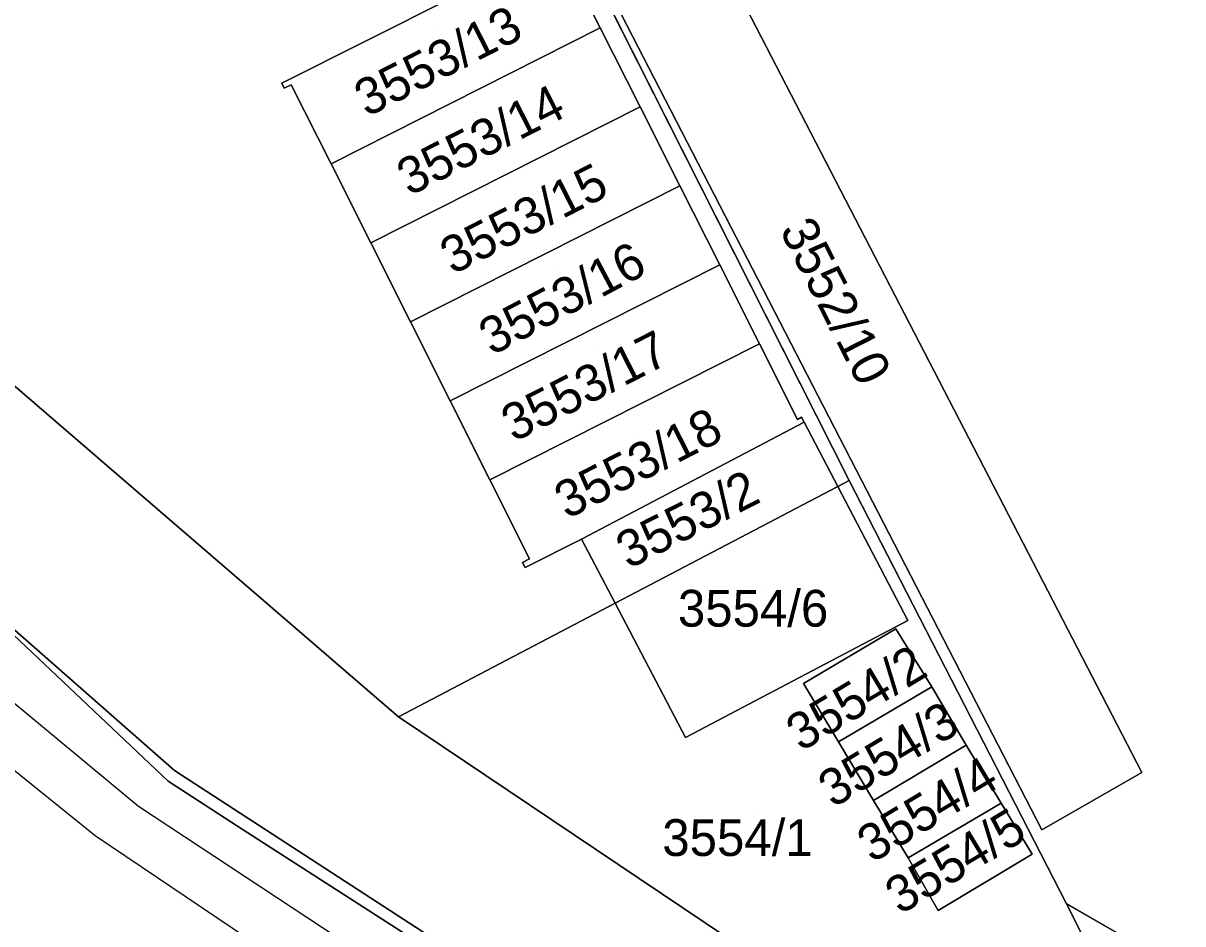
# Model space of a CAD drawing. Extents: x -262657 to -261595, y -1238015 to -1237156.
# Drawn here: x -262494.6 to -262431.6, y -1237484.4 to -1237435.4 of the extents above; entities that cross this region are included whole.
import ezdxf

# ---------------------------------------------------------------- set-up
doc = ezdxf.new("R2010")
doc.units = 0
for name, color, linetype in [('body_kn', 7, 'Continuous'), ('kladpar_druhypozemkov', 7, 'Continuous'), ('kladpar_hranice', 7, 'Continuous'), ('kladpar_parcelnecisla', 7, 'Continuous'), ('kladpar_plochy', 7, 'Continuous'), ('zappar_hrandruhpozemk', 7, 'Continuous')]:
    doc.layers.add(name, color=color, linetype=linetype)

msp = doc.modelspace()

# ---------------------------------------------------------------- linework, layer by layer
at = {"layer": 'body_kn'}
for p, q in [((-262463.26, -1237435.69), (-262463.26, -1237435.69)), ((-262463.26, -1237435.69), (-262463.26, -1237435.69)), ((-262480.58, -1237438.69), (-262480.58, -1237438.69)), ((-262480.44, -1237438.97), (-262480.44, -1237438.97)), ((-262480.06, -1237438.78), (-262480.06, -1237438.78)), ((-262461.09, -1237439.99), (-262461.09, -1237439.99)), ((-262461.09, -1237439.99), (-262461.09, -1237439.99)), ((-262477.9, -1237443.08), (-262477.9, -1237443.08)), ((-262458.93, -1237444.28), (-262458.93, -1237444.28)), ((-262458.93, -1237444.28), (-262458.93, -1237444.28)), ((-262475.74, -1237447.37), (-262475.74, -1237447.37)), ((-262456.76, -1237448.58), (-262456.76, -1237448.58)), ((-262456.76, -1237448.58), (-262456.76, -1237448.58)), ((-262473.58, -1237451.67), (-262473.58, -1237451.67)), ((-262454.6, -1237452.87), (-262454.6, -1237452.87)), ((-262454.6, -1237452.87), (-262454.6, -1237452.87)), ((-262471.42, -1237455.97), (-262471.42, -1237455.97)), ((-262452.53, -1237456.98), (-262452.53, -1237456.98)), ((-262452.31, -1237456.86), (-262452.31, -1237456.86)), ((-262452.17, -1237457.13), (-262452.17, -1237457.13)), ((-262469.26, -1237460.27), (-262469.26, -1237460.27)), ((-262450.34, -1237460.63), (-262450.34, -1237460.63)), ((-262449.72, -1237460.31), (-262449.72, -1237460.31)), ((-262464.28, -1237463.5), (-262464.28, -1237463.5)), ((-262467.1, -1237464.57), (-262467.1, -1237464.57)), ((-262467.48, -1237464.76), (-262467.48, -1237464.76)), ((-262467.34, -1237465.04), (-262467.34, -1237465.04)), ((-262462.45, -1237466.98), (-262462.45, -1237466.98)), ((-262446.52, -1237467.91), (-262446.52, -1237467.91)), ((-262447.18, -1237468.37), (-262447.18, -1237468.37)), ((-262452.2, -1237471.34), (-262452.2, -1237471.34)), ((-262445.23, -1237471.53), (-262445.23, -1237471.53)), ((-262474.23, -1237473.15), (-262474.23, -1237473.15)), ((-262458.62, -1237474.27), (-262458.62, -1237474.27)), ((-262450.3, -1237474.52), (-262450.3, -1237474.52)), ((-262450.3, -1237474.52), (-262450.3, -1237474.52)), ((-262443.36, -1237474.7), (-262443.36, -1237474.7)), ((-262486.42, -1237476.08), (-262486.42, -1237476.08)), ((-262433.8, -1237476.18), (-262433.8, -1237476.18)), ((-262486.75, -1237476.66), (-262486.75, -1237476.66)), ((-262448.4, -1237477.7), (-262448.4, -1237477.7)), ((-262488.38, -1237478.01), (-262488.38, -1237478.01)), ((-262488.38, -1237478.01), (-262488.38, -1237478.01)), ((-262441.45, -1237477.85), (-262441.45, -1237477.85)), ((-262441.45, -1237477.85), (-262441.45, -1237477.85)), ((-262490.72, -1237479.63), (-262490.72, -1237479.63)), ((-262482.67, -1237479.3), (-262482.67, -1237479.3)), ((-262439.24, -1237479.29), (-262439.24, -1237479.29)), ((-262446.51, -1237480.83), (-262446.51, -1237480.83)), ((-262439.76, -1237480.62), (-262439.76, -1237480.62)), ((-262437.9, -1237483.33), (-262437.9, -1237483.33)), ((-262437.9, -1237483.33), (-262437.9, -1237483.33)), ((-262444.88, -1237483.68), (-262444.88, -1237483.68))]:
    msp.add_line(p, q, dxfattribs=at)
at = {"layer": 'kladpar_druhypozemkov'}
for p, q in [((-262472.01, -1237435.78), (-262472.01, -1237435.78)), ((-262470.02, -1237440.27), (-262470.02, -1237440.27)), ((-262467.87, -1237444.74), (-262467.87, -1237444.74)), ((-262465.57, -1237448.92), (-262465.57, -1237448.92)), ((-262449.78, -1237450.42), (-262449.78, -1237450.42)), ((-262463.49, -1237453.15), (-262463.49, -1237453.15)), ((-262461.19, -1237457.73), (-262461.19, -1237457.73)), ((-262458.49, -1237461.26), (-262458.49, -1237461.26)), ((-262454.52, -1237466.22), (-262454.52, -1237466.22)), ((-262449.49, -1237470.42), (-262449.49, -1237470.42)), ((-262447.56, -1237473.71), (-262447.56, -1237473.71)), ((-262445.67, -1237477.1), (-262445.67, -1237477.1)), ((-262454.87, -1237478.37), (-262454.87, -1237478.37)), ((-262443.64, -1237480.28), (-262443.64, -1237480.28))]:
    msp.add_line(p, q, dxfattribs=at)
at = {"layer": 'kladpar_hranice'}
msp.add_line((-262428.89, -1237501.14), (-262437.9, -1237483.33), dxfattribs=at)
for points in [[(-262437.9, -1237483.33), (-262449.72, -1237460.31), (-262464.28, -1237431.46), (-262469.6, -1237420.93), (-262478.29, -1237403.67), (-262478.73, -1237402.85), (-262506.09, -1237404.44), (-262514.95, -1237386.75), (-262519.84, -1237377.16), (-262513.51, -1237373.66), (-262507.3, -1237370.26), (-262500.71, -1237366.65), (-262500.15, -1237367.7), (-262490.13, -1237386.72), (-262486.03, -1237384.56), (-262484.61, -1237387.26), (-262481.8, -1237385.78), (-262483.22, -1237383.08), (-262479.4, -1237381.2)], [(-262395.88, -1237531.76), (-262402.36, -1237530.54), (-262422.32, -1237519.41), (-262447.06, -1237506.81), (-262470.88, -1237493), (-262490.72, -1237479.63), (-262514.25, -1237460.66), (-262531.79, -1237443.64), (-262573.35, -1237398.14), (-262590.88, -1237375.27)], [(-262562.79, -1237383.63), (-262550.17, -1237397.64), (-262523.77, -1237426.48), (-262525.24, -1237427.48), (-262521.65, -1237431.15), (-262511.59, -1237440.19), (-262501.92, -1237449.31), (-262474.23, -1237473.15), (-262426.57, -1237505.16), (-262417.76, -1237512.55), (-262418.9, -1237513.84), (-262420.4, -1237513.14), (-262442.59, -1237502.2), (-262453.27, -1237496.92), (-262463.93, -1237490.63), (-262472.55, -1237485.09), (-262486.42, -1237476.08), (-262499.91, -1237464.23)], [(-262576.16, -1237389.82), (-262565.17, -1237400.69), (-262553.5, -1237412.44), (-262535.69, -1237430.45), (-262521.77, -1237443.76), (-262511.25, -1237453.79), (-262499.91, -1237464.23), (-262486.75, -1237476.66), (-262482.67, -1237479.3), (-262464.31, -1237491.1), (-262455.93, -1237496.51), (-262449.45, -1237500.04), (-262419.93, -1237515), (-262406.23, -1237521.95), (-262395.88, -1237531.76)], [(-262501.01, -1237414.95), (-262493.57, -1237411.26), (-262490.55, -1237417.14), (-262482.07, -1237412.85), (-262480.81, -1237415.34), (-262479.46, -1237418.02), (-262478.12, -1237420.68), (-262476.78, -1237423.32), (-262475.43, -1237425.99), (-262474.07, -1237428.68), (-262472.71, -1237431.38), (-262471.37, -1237434.05), (-262480.58, -1237438.69), (-262480.44, -1237438.97), (-262480.06, -1237438.78), (-262477.9, -1237443.08), (-262475.74, -1237447.37), (-262473.58, -1237451.67), (-262471.42, -1237455.97), (-262469.26, -1237460.27), (-262467.1, -1237464.57), (-262467.48, -1237464.76), (-262467.34, -1237465.04), (-262464.28, -1237463.5)], [(-262465.7, -1237431.19), (-262465.34, -1237431.01), (-262465.21, -1237431.27), (-262465.43, -1237431.39), (-262463.26, -1237435.69), (-262477.9, -1237443.08), (-262480.06, -1237438.78), (-262480.44, -1237438.97), (-262480.58, -1237438.69), (-262471.37, -1237434.05), (-262465.7, -1237431.19)], [(-262464.28, -1237431.46), (-262449.72, -1237460.31), (-262450.34, -1237460.63), (-262452.17, -1237457.13), (-262452.31, -1237456.86), (-262452.53, -1237456.98), (-262454.6, -1237452.87), (-262456.76, -1237448.58), (-262458.93, -1237444.28), (-262461.09, -1237439.99), (-262463.26, -1237435.69), (-262465.43, -1237431.39)], [(-262462.11, -1237434.98), (-262456.65, -1237432.03), (-262433.8, -1237476.18), (-262439.24, -1237479.29), (-262462.11, -1237434.98)], [(-262456.65, -1237432.03), (-262462.11, -1237434.98), (-262439.24, -1237479.29), (-262433.8, -1237476.18), (-262456.65, -1237432.03)], [(-262463.26, -1237435.69), (-262461.09, -1237439.99), (-262475.74, -1237447.37), (-262477.9, -1237443.08), (-262463.26, -1237435.69)], [(-262461.09, -1237439.99), (-262458.93, -1237444.28), (-262473.58, -1237451.67), (-262475.74, -1237447.37), (-262461.09, -1237439.99)], [(-262458.93, -1237444.28), (-262456.76, -1237448.58), (-262471.42, -1237455.97), (-262473.58, -1237451.67), (-262458.93, -1237444.28)], [(-262456.76, -1237448.58), (-262454.6, -1237452.87), (-262469.26, -1237460.27), (-262471.42, -1237455.97), (-262456.76, -1237448.58)], [(-262464.28, -1237463.5), (-262462.45, -1237466.98), (-262474.23, -1237473.15), (-262501.92, -1237449.31)], [(-262454.6, -1237452.87), (-262452.53, -1237456.98), (-262452.31, -1237456.86), (-262452.17, -1237457.13), (-262464.28, -1237463.5), (-262467.34, -1237465.04), (-262467.48, -1237464.76), (-262467.1, -1237464.57), (-262469.26, -1237460.27), (-262454.6, -1237452.87)], [(-262450.34, -1237460.63), (-262462.45, -1237466.98), (-262464.28, -1237463.5), (-262452.17, -1237457.13), (-262450.34, -1237460.63)], [(-262428.89, -1237501.14), (-262426.57, -1237505.16), (-262474.23, -1237473.15), (-262462.45, -1237466.98), (-262458.62, -1237474.27), (-262446.52, -1237467.91), (-262450.34, -1237460.63), (-262449.72, -1237460.31), (-262437.9, -1237483.33), (-262428.89, -1237501.14)], [(-262462.45, -1237466.98), (-262450.34, -1237460.63), (-262446.52, -1237467.91), (-262458.62, -1237474.27), (-262462.45, -1237466.98)], [(-262419.93, -1237515), (-262449.45, -1237500.04), (-262455.93, -1237496.51), (-262464.31, -1237491.1), (-262482.67, -1237479.3), (-262486.75, -1237476.66), (-262499.91, -1237464.23), (-262486.42, -1237476.08), (-262472.55, -1237485.09), (-262463.93, -1237490.63), (-262453.27, -1237496.92), (-262442.59, -1237502.2), (-262420.4, -1237513.14), (-262418.9, -1237513.84), (-262419.93, -1237515)], [(-262450.3, -1237474.52), (-262452.2, -1237471.34), (-262447.18, -1237468.37), (-262445.23, -1237471.53), (-262450.3, -1237474.52)], [(-262439.76, -1237480.62), (-262441.45, -1237477.85), (-262443.36, -1237474.7), (-262445.23, -1237471.53), (-262447.18, -1237468.37), (-262452.2, -1237471.34), (-262450.3, -1237474.52), (-262448.4, -1237477.7), (-262446.51, -1237480.83), (-262444.88, -1237483.68), (-262439.76, -1237480.62)], [(-262450.3, -1237474.52), (-262445.23, -1237471.53), (-262443.36, -1237474.7), (-262448.4, -1237477.7), (-262450.3, -1237474.52)], [(-262441.45, -1237477.85), (-262446.51, -1237480.83), (-262448.4, -1237477.7), (-262443.36, -1237474.7), (-262441.45, -1237477.85)], [(-262441.45, -1237477.85), (-262439.76, -1237480.62), (-262444.88, -1237483.68), (-262446.51, -1237480.83), (-262441.45, -1237477.85)], [(-262437.9, -1237483.33), (-262420.61, -1237493.26), (-262428.89, -1237501.14)], [(-262408.93, -1237499.96), (-262420.61, -1237493.26), (-262437.9, -1237483.33)]]:
    msp.add_lwpolyline(points, dxfattribs=at)
at = {"layer": 'kladpar_plochy'}
for p, q in [((-262449.72, -1237460.31), (-262464.28, -1237431.46)), ((-262433.8, -1237476.18), (-262456.65, -1237432.03)), ((-262462.11, -1237434.98), (-262439.24, -1237479.29)), ((-262450.34, -1237460.63), (-262449.72, -1237460.31)), ((-262446.52, -1237467.91), (-262450.34, -1237460.63)), ((-262437.9, -1237483.33), (-262449.72, -1237460.31)), ((-262449.72, -1237460.31), (-262437.9, -1237483.33)), ((-262474.23, -1237473.15), (-262462.45, -1237466.98)), ((-262462.45, -1237466.98), (-262458.62, -1237474.27)), ((-262458.62, -1237474.27), (-262446.52, -1237467.91)), ((-262447.18, -1237468.37), (-262452.2, -1237471.34)), ((-262445.23, -1237471.53), (-262447.18, -1237468.37)), ((-262452.2, -1237471.34), (-262450.3, -1237474.52)), ((-262443.36, -1237474.7), (-262445.23, -1237471.53)), ((-262426.57, -1237505.16), (-262474.23, -1237473.15)), ((-262450.3, -1237474.52), (-262448.4, -1237477.7)), ((-262441.45, -1237477.85), (-262443.36, -1237474.7)), ((-262439.24, -1237479.29), (-262433.8, -1237476.18)), ((-262448.4, -1237477.7), (-262446.51, -1237480.83)), ((-262439.76, -1237480.62), (-262441.45, -1237477.85)), ((-262446.51, -1237480.83), (-262444.88, -1237483.68)), ((-262444.88, -1237483.68), (-262439.76, -1237480.62)), ((-262420.61, -1237493.26), (-262437.9, -1237483.33)), ((-262437.9, -1237483.33), (-262428.89, -1237501.14))]:
    msp.add_line(p, q, dxfattribs=at)
for points in [[(-262395.88, -1237531.76), (-262402.36, -1237530.54), (-262422.32, -1237519.41), (-262447.06, -1237506.81), (-262470.88, -1237493), (-262490.72, -1237479.63), (-262514.25, -1237460.66), (-262531.79, -1237443.64), (-262573.35, -1237398.14), (-262590.88, -1237375.27), (-262576.16, -1237389.82), (-262565.17, -1237400.69), (-262553.5, -1237412.44), (-262535.69, -1237430.45), (-262521.77, -1237443.76), (-262511.25, -1237453.79), (-262499.91, -1237464.23), (-262486.75, -1237476.66), (-262482.67, -1237479.3), (-262464.31, -1237491.1), (-262455.93, -1237496.51), (-262449.45, -1237500.04), (-262419.93, -1237515), (-262406.23, -1237521.95)], [(-262465.7, -1237431.19), (-262465.34, -1237431.01), (-262465.21, -1237431.27), (-262465.43, -1237431.39), (-262463.26, -1237435.69), (-262477.9, -1237443.08), (-262480.06, -1237438.78), (-262480.44, -1237438.97), (-262480.58, -1237438.69), (-262471.37, -1237434.05)], [(-262462.11, -1237434.98), (-262456.65, -1237432.03), (-262433.8, -1237476.18), (-262439.24, -1237479.29)], [(-262463.26, -1237435.69), (-262461.09, -1237439.99), (-262475.74, -1237447.37), (-262477.9, -1237443.08)], [(-262461.09, -1237439.99), (-262458.93, -1237444.28), (-262473.58, -1237451.67), (-262475.74, -1237447.37)], [(-262458.93, -1237444.28), (-262456.76, -1237448.58), (-262471.42, -1237455.97), (-262473.58, -1237451.67)], [(-262456.76, -1237448.58), (-262454.6, -1237452.87), (-262469.26, -1237460.27), (-262471.42, -1237455.97)], [(-262454.6, -1237452.87), (-262452.53, -1237456.98), (-262452.31, -1237456.86), (-262452.17, -1237457.13), (-262464.28, -1237463.5), (-262467.34, -1237465.04), (-262467.48, -1237464.76), (-262467.1, -1237464.57), (-262469.26, -1237460.27)], [(-262450.34, -1237460.63), (-262462.45, -1237466.98), (-262464.28, -1237463.5), (-262452.17, -1237457.13)], [(-262462.45, -1237466.98), (-262450.34, -1237460.63), (-262446.52, -1237467.91), (-262458.62, -1237474.27)], [(-262419.93, -1237515), (-262449.45, -1237500.04), (-262455.93, -1237496.51), (-262464.31, -1237491.1), (-262482.67, -1237479.3), (-262486.75, -1237476.66), (-262499.91, -1237464.23), (-262486.42, -1237476.08), (-262472.55, -1237485.09), (-262463.93, -1237490.63), (-262453.27, -1237496.92), (-262442.59, -1237502.2), (-262420.4, -1237513.14), (-262418.9, -1237513.84)], [(-262450.3, -1237474.52), (-262452.2, -1237471.34), (-262447.18, -1237468.37), (-262445.23, -1237471.53)], [(-262450.3, -1237474.52), (-262445.23, -1237471.53), (-262443.36, -1237474.7), (-262448.4, -1237477.7)], [(-262441.45, -1237477.85), (-262446.51, -1237480.83), (-262448.4, -1237477.7), (-262443.36, -1237474.7)], [(-262441.45, -1237477.85), (-262439.76, -1237480.62), (-262444.88, -1237483.68), (-262446.51, -1237480.83)], [(-262428.89, -1237501.14), (-262437.9, -1237483.33), (-262420.61, -1237493.26)]]:
    msp.add_lwpolyline(points, close=True, dxfattribs=at)
for points in [[(-262562.79, -1237383.63), (-262550.17, -1237397.64), (-262523.77, -1237426.48), (-262525.24, -1237427.48), (-262521.65, -1237431.15), (-262511.59, -1237440.19), (-262501.92, -1237449.31), (-262474.23, -1237473.15), (-262426.57, -1237505.16), (-262417.76, -1237512.55), (-262418.9, -1237513.84), (-262420.4, -1237513.14), (-262442.59, -1237502.2), (-262453.27, -1237496.92), (-262463.93, -1237490.63), (-262472.55, -1237485.09), (-262486.42, -1237476.08), (-262499.91, -1237464.23), (-262511.25, -1237453.79), (-262521.77, -1237443.76), (-262535.69, -1237430.45), (-262552.09, -1237410.69), (-262573.78, -1237386.21)], [(-262464.28, -1237431.46), (-262449.72, -1237460.31), (-262450.34, -1237460.63), (-262452.17, -1237457.13), (-262452.31, -1237456.86), (-262452.53, -1237456.98), (-262454.6, -1237452.87), (-262456.76, -1237448.58), (-262458.93, -1237444.28), (-262461.09, -1237439.99), (-262463.26, -1237435.69), (-262465.43, -1237431.39)], [(-262471.37, -1237434.05), (-262480.58, -1237438.69), (-262480.44, -1237438.97), (-262480.06, -1237438.78), (-262477.9, -1237443.08), (-262475.74, -1237447.37), (-262473.58, -1237451.67), (-262471.42, -1237455.97), (-262469.26, -1237460.27), (-262467.1, -1237464.57), (-262467.48, -1237464.76), (-262467.34, -1237465.04), (-262464.28, -1237463.5), (-262462.45, -1237466.98), (-262474.23, -1237473.15), (-262501.92, -1237449.31)]]:
    msp.add_lwpolyline(points, dxfattribs=at)
at = {"layer": 'zappar_hrandruhpozemk'}
msp.add_line((-262512.38, -1237458.13), (-262488.38, -1237478.01), dxfattribs=at)
msp.add_lwpolyline([(-262488.38, -1237478.01), (-262468.36, -1237491.2), (-262452.47, -1237499.96)], dxfattribs=at)

# ---------------------------------------------------------------- texts
at = {"layer": 'kladpar_parcelnecisla'}
for s, rotation, p in [('3553/13', 27, (-262475.947, -1237440.565)), ('3553/14', 27, (-262473.636, -1237444.858)), ('3553/15', 27, (-262471.285, -1237449.133)), ('3552/10', 297, (-262453.525, -1237446.68)), ('3553/16', 28, (-262469.145, -1237453.536)), ('3553/17', 27, (-262467.954, -1237458.237)), ('3553/18', 27, (-262465.067, -1237462.429)), ('3553/2', 27, (-262461.715, -1237465.145)), ('3554/2', 31, (-262452.339, -1237475.079)), ('3554/3', 31, (-262450.592, -1237478.137)), ('3554/4', 31, (-262448.474, -1237481.135)), ('3554/5', 31, (-262446.952, -1237483.943))]:
    msp.add_text(s, height=2, rotation=rotation, dxfattribs=at).set_placement(p)
for s, p in [('3554/6', (-262459.033, -1237468.25)), ('3554/1', (-262459.883, -1237480.72))]:
    msp.add_text(s, height=2, dxfattribs=at).set_placement(p)

doc.saveas('drawing.dxf')
